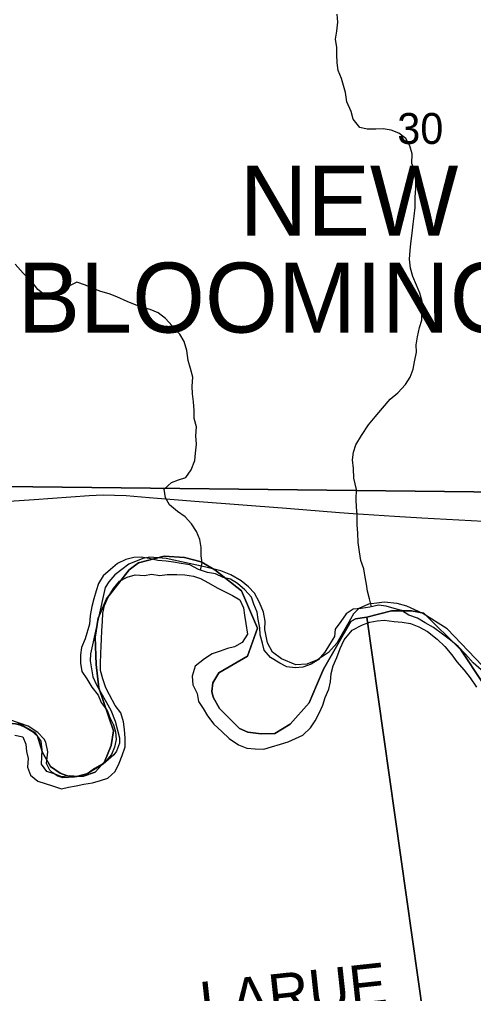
# Model space of a CAD drawing. Extents: x 1584893 to 1934202, y 663575 to 1091909.
# Drawn here: x 1744832 to 1748072, y 934048 to 941008 of the extents above; entities that cross this region are included whole.
import ezdxf

# ---------------------------------------------------------------- set-up
doc = ezdxf.new("R2010")
doc.units = 0
for name, color, linetype in [('GM_X_Corporation_Text', 7, 'Continuous'), ('GM_X_County_Road', 7, 'Continuous'), ('GM_X_County_Road_Text', 7, 'Continuous'), ('GM_X_Major_River', 7, 'Continuous'), ('GM_X_Minor_River', 7, 'Continuous'), ('GM_X_Section', 7, 'Continuous'), ('GM_X_Section_Text', 7, 'Continuous'), ('GM_X_Township', 7, 'Continuous')]:
    doc.layers.add(name, color=color, linetype=linetype)

msp = doc.modelspace()

# ---------------------------------------------------------------- linework, layer by layer
at = {"layer": 'GM_X_County_Road'}
for points in [[(1744705.4, 937566.6), (1744793.6, 937568.8), (1744936.5, 937577.9), (1745198.9, 937597.8), (1745330, 937606.9), (1745428.6, 937610.5), (1745510.8, 937610.1), (1745593, 937606.2), (1745756.7, 937593.6), (1746083.8, 937567), (1746738.2, 937515.2), (1747114.5, 937485.3), (1747212.4, 937478.5)], [(1747212.4, 937478.5), (1747507.4, 937458.3), (1747703.9, 937447.4), (1748408.5, 937408)]]:
    msp.add_lwpolyline(points, dxfattribs=at)
at = {"layer": 'GM_X_Major_River'}
for points in [[(1745878.1, 937137.5), (1745820.2, 937142.4), (1745756.3, 937155.5), (1745700.4, 937166.4), (1745648.3, 937163.3), (1745590, 937150.2), (1745531.5, 937121.1), (1745480.7, 937077.8), (1745429.9, 937032.5), (1745395, 936979), (1745378.1, 936925.1), (1745363.1, 936867.2), (1745348.2, 936813.3), (1745337.2, 936749.3), (1745330.2, 936687.3), (1745300.4, 936583.5), (1745273.3, 936519.8), (1745266.5, 936467.8), (1745267.5, 936409.7), (1745276.6, 936349.3), (1745311.8, 936296.7), (1745348.8, 936237.9), (1745393.9, 936179), (1745415.1, 936126.5), (1745458.2, 936069.7), (1745475.4, 936019.3), (1745502.6, 935968.7), (1745517.8, 935918.3), (1745520.9, 935862.1), (1745510, 935808.2), (1745489.2, 935756.4), (1745438.1, 935697.1), (1745367.4, 935656.1), (1745314.7, 935618.9), (1745250.3, 935599.9), (1745190.3, 935602.9), (1745134.1, 935595.8), (1745078.4, 935616.8), (1745026.6, 935635.7), (1744989.4, 935686.4), (1744990.3, 935740.5), (1744993.1, 935790.6), (1744986.1, 935850.9), (1744945, 935907.7), (1744893.4, 935940.6), (1744841.8, 935963.5), (1744783.9, 935978.5)], [(1748126.1, 936360.7), (1748068.9, 936411.8), (1748015.8, 936472.8), (1747962.7, 936527.8), (1747907.3, 936572.8), (1747852, 936615.8), (1747786.7, 936663), (1747727.1, 936696.1), (1747671.6, 936729.1), (1747609.9, 936752.2), (1747558.4, 936785.1), (1747506.6, 936800), (1747448.8, 936816.9), (1747394.8, 936823.8), (1747332.5, 936808.8), (1747270.3, 936799.8), (1747214.1, 936794.7), (1747163.5, 936761.5), (1747124.6, 936706), (1747083.6, 936650.5), (1747080.8, 936600.4), (1747043.8, 936540.9), (1747010.9, 936487.3), (1746963.9, 936431.9), (1746913.3, 936400.7), (1746854.9, 936379.6), (1746798.8, 936376.5), (1746740.9, 936383.5), (1746689.2, 936408.4), (1746623.8, 936449.5), (1746578.6, 936500.4), (1746565.4, 936550.8), (1746548.4, 936611.2), (1746547.2, 936661.3), (1746536.1, 936721.7), (1746529, 936773.9), (1746503.9, 936830.5), (1746486.7, 936880.9), (1746439.5, 936933.8), (1746388.2, 936978.7), (1746336.6, 937009.6), (1746284.7, 937020.5), (1746231.1, 937047.5), (1746173.2, 937056.4), (1746109.5, 937077.5), (1746047.9, 937110.6), (1745986, 937121.7), (1745930.1, 937130.6), (1745878.1, 937137.5)], [(1744798.6, 935894), (1744856.5, 935883.1), (1744877.6, 935830.6), (1744880.8, 935778.4), (1744894, 935728.1), (1744889, 935666), (1744910, 935607.5), (1744963.4, 935566.5), (1745067, 935532.7), (1745130.7, 935511.7), (1745181, 935522.8), (1745235.2, 935532), (1745291.4, 935543.1), (1745351.7, 935554.1), (1745410, 935569.2), (1745462.3, 935586.4), (1745515.2, 935633.7), (1745544.2, 935695.3), (1745565.1, 935749.1), (1745586.2, 935810.9), (1745585.2, 935873.1), (1745582.2, 935935.3), (1745573.1, 935989.6), (1745554.1, 936054.1), (1745514.9, 936106.8), (1745474.1, 936181.7), (1745446.9, 936232.3), (1745425.9, 936296.8), (1745410.8, 936355.2), (1745409.7, 936407.3), (1745412.8, 936477.4), (1745413.7, 936529.6), (1745416.5, 936579.6), (1745419.5, 936641.7), (1745424.6, 936705.8), (1745425.5, 936765.9), (1745438.4, 936819.9), (1745465.5, 936879.6), (1745502.5, 936941.1), (1745545.4, 936994.6), (1745600, 937023.7), (1745656.3, 937040.9), (1745724.3, 937035.7), (1745774.5, 937044.9), (1745834.4, 937035.9), (1745884.6, 937041.1), (1745954.7, 937042), (1746012.7, 937039), (1746072.6, 937030), (1746124.4, 937013.1), (1746180, 936982.1), (1746243.5, 936947), (1746299.1, 936918), (1746352.7, 936893.1), (1746404.2, 936860.2), (1746429.4, 936803.6), (1746436.5, 936751.4), (1746447.6, 936693), (1746458.3, 936616.7), (1746421.3, 936557.1), (1746366.7, 936525.9), (1746316.5, 936512.7), (1746264.1, 936495.5), (1746207.7, 936474.4), (1746153.1, 936439.2), (1746086.1, 936386.2), (1746065, 936316.4), (1746070, 936254.1), (1746099, 936191.5), (1746110.1, 936135.2), (1746143.3, 936084.5), (1746172.5, 936031.9), (1746217.6, 935973), (1746274.8, 935919.9), (1746328, 935870.9), (1746395.4, 935825.7), (1746455, 935800.7), (1746513, 935795.7), (1746575.1, 935794.7), (1746629.4, 935809.8), (1746693.8, 935830.8), (1746750.1, 935845.9), (1746802.6, 935871.2), (1746853, 935894.4), (1746907.9, 935945.6), (1746942.8, 935997.2), (1746971.7, 936050.8), (1746996.7, 936108.6), (1747013.6, 936162.4), (1747038.6, 936222.2), (1747051.5, 936276.1), (1747056.4, 936334.2), (1747069.4, 936390.1), (1747096.4, 936449.8), (1747121.4, 936513.5), (1747148.5, 936575.3), (1747205.7, 936644.5)], [(1747205.7, 936644.5), (1747280.4, 936683.4), (1747332.7, 936700.5), (1747385, 936711.7), (1747435.1, 936714.9), (1747507, 936705.7), (1747563, 936702.8), (1747622.9, 936691.8), (1747682.6, 936668.8), (1747744.2, 936635.7), (1747813.3, 936580.4), (1747866.5, 936527.4), (1747917.6, 936468.4), (1747952.9, 936417.7), (1748006, 936358.7), (1748049.1, 936303.8), (1748094.1, 936236.9)]]:
    msp.add_lwpolyline(points, dxfattribs=at)
at = {"layer": 'GM_X_Minor_River'}
for points in [[(1747344.6, 936811.7), (1747329.5, 936869), (1747314.4, 936923.4), (1747309.2, 936973.6), (1747300, 937023.9), (1747288.9, 937082.2), (1747267.9, 937142.7), (1747258.9, 937205), (1747250, 937271.3), (1747247, 937337.5), (1747242, 937397.8), (1747241.2, 937470), (1747238, 937522.2), (1747235, 937578.3), (1747238.1, 937648.5), (1747217.4, 937731), (1747216.5, 937799.2), (1747209.6, 937861.5), (1747214.5, 937917.5), (1747231.3, 937969.4), (1747272.5, 938034.9), (1747321.8, 938112.3), (1747370.8, 938169.6), (1747421.8, 938230.9), (1747477, 938296.2), (1747531.8, 938341.4), (1747586.8, 938400.6), (1747619.7, 938452.2), (1747640.7, 938510), (1747651.5, 938562), (1747664.7, 938629.9), (1747663.5, 938682.1), (1747672.5, 938740.1), (1747687.6, 938806), (1747704.5, 938859.8), (1747706.7, 938994.1), (1747689.6, 939052.5), (1747664.5, 939109.1), (1747639.5, 939171.7), (1747622.4, 939230.1), (1747615.5, 939294.3), (1747620.5, 939356.4), (1747625.3, 939408.5), (1747634.5, 939480.5), (1747641.6, 939544.5), (1747648.6, 939602.6), (1747655.6, 939664.6), (1747656.8, 939738.8), (1747659.8, 939800.9), (1747660.7, 939857), (1747649.9, 939929.3), (1747632.7, 939979.7), (1747633.8, 940047.9), (1747618.8, 940106.3), (1747589.6, 940156.9), (1747538.1, 940195.8), (1747484.4, 940216.7), (1747428.5, 940227.7), (1747374.4, 940224.6), (1747312.3, 940223.6), (1747260.5, 940236.4), (1747213.4, 940295.4), (1747198.3, 940349.7), (1747167.4, 940420.4), (1747158.5, 940486.7), (1747143.3, 940537.1), (1747130.1, 940587.4), (1747105, 940644), (1747097.9, 940698.2), (1747096.8, 940758.4), (1747095.7, 940808.5), (1747086.6, 940866.8), (1747097.6, 940924.8), (1747102.6, 940988.8), (1747099.6, 941047)], [(1746123.4, 937072.9), (1746136.3, 937125.2), (1746129.1, 937175.4), (1746128, 937235.6), (1746119, 937291.9), (1746095.9, 937348.4), (1746058.7, 937403.2), (1746013.5, 937454), (1745960.1, 937493), (1745902.8, 937540.1), (1745873.5, 937590.7), (1745864.6, 937653), (1745915.4, 937700.2), (1745965.8, 937719.5), (1746018.1, 937734.7), (1746057, 937790.2), (1746082.1, 937855.9), (1746087, 937910), (1746094.1, 937974), (1746091, 938034.2), (1746094.1, 938096.3), (1746079, 938156.7), (1746078, 938212.9), (1746073, 938277.1), (1746065.9, 938333.4), (1746064.8, 938387.5), (1746067.8, 938451.6), (1746052.9, 938514), (1746035.8, 938572.4), (1746026.9, 938642.8), (1746006, 938707.2), (1745976.8, 938759.9), (1745921.7, 938818.9), (1745874.5, 938871.8), (1745821.1, 938910.8), (1745765.4, 938935.7), (1745709.6, 938950.7), (1745651.9, 938971.7), (1745600.1, 938992.6), (1745526.6, 939025.9), (1745470.9, 939046.8), (1745413.1, 939063.8), (1745355.4, 939084.8), (1745301.7, 939109.8), (1745242, 939130.8), (1745183.4, 939101.7), (1745132.8, 939064.4), (1745068.3, 939039.4), (1745018.2, 939036.2), (1744962.8, 939079.2), (1744917.7, 939138.1), (1744858.6, 939195.2), (1744799.6, 939260.3)]]:
    msp.add_lwpolyline(points, dxfattribs=at)
at = {"layer": 'GM_X_Section'}
msp.add_lwpolyline([(1744794.1, 942974), (1750676.5, 942925.4), (1750594.8, 937603.3), (1744716.7, 937672), (1744790.8, 942835.4)], close=True, dxfattribs=at)
for points in [[(1744716.7, 937672), (1750594.8, 937603.3)], [(1748187.1, 936336.7), (1747883.9, 936653.5), (1747710.9, 936763.1), (1747597.4, 936816.1), (1747527.5, 936834.7), (1747435.6, 936843.5), (1747400, 936839.5), (1747321.5, 936830.5), (1747253.1, 936799.2), (1747214.8, 936761.5), (1747172.1, 936685.9), (1747096.9, 936550.5), (1747038.3, 936485), (1746957.8, 936431.7), (1746881.6, 936402.4), (1746803.5, 936397.1), (1746701.9, 936440), (1746636.3, 936486.6), (1746600.9, 936555), (1746583.7, 936649.1), (1746584.3, 936709.1), (1746572.8, 936773.2), (1746545.4, 936841.5), (1746510, 936907.8), (1746466.4, 936954.2), (1746412.8, 936996.7), (1746341.2, 937039.3), (1746269.4, 937068), (1746151.7, 937097), (1745878.2, 937157.5), (1745762.3, 937166.5), (1745712.2, 937157), (1745611.8, 937115.9), (1745513.1, 937040.8), (1745468.6, 936989.1), (1745442.3, 936949.4), (1745338, 936474.2), (1745335.5, 936424.3), (1745354.5, 936310.1), (1745382, 936253.8), (1745484.4, 936072.9), (1745513.7, 935994.6), (1745544.7, 935876.3), (1745544.3, 935836.3), (1745523.8, 935780.5), (1745505.5, 935752.7), (1745429, 935687.3), (1745318.3, 935620.3), (1745222.1, 935595.2), (1745140.1, 935589.9), (1745104.2, 935602.2), (1745064.4, 935626.6), (1745048.5, 935644.7), (1745025, 935692.9), (1745033.7, 935774.9), (1745020.3, 935845), (1745008.5, 935865.1), (1744962.9, 935913.5), (1744893.3, 935958.1), (1744691.9, 936028)]]:
    msp.add_lwpolyline(points, dxfattribs=at)
at = {"layer": 'GM_X_Township'}
for points in [[(1748137.4, 936270.1), (1747980.9, 936503.1), (1747716.7, 936765.1), (1747628.7, 936781.6), (1747486.9, 936782.6), (1747310.8, 936737), (1747230.1, 936725.5), (1747197, 936706.9), (1747001.4, 936364.9), (1746950.7, 936248.9), (1746900.1, 936124.5), (1746764.4, 935973.3), (1746654.7, 935906.9), (1746557.4, 935902.8), (1746462.1, 935915.2), (1746401, 935942), (1746258, 936084.9), (1746213.5, 936165.7), (1746205.1, 936207.2), (1746212.4, 936267.2), (1746253.8, 936339.8), (1746458.8, 936457.9), (1746530.1, 936659.9), (1746416.2, 936926), (1746225.5, 937075.1), (1746129.2, 937133.1), (1746009.1, 937163.1), (1745864.1, 937173.3), (1745680.9, 937124.6), (1745614.6, 937075.9), (1745452, 936868.6), (1745393.1, 936730.9), (1745371.4, 936594.2), (1745378.7, 936399.4), (1745397.5, 936231.7), (1745503.3, 935925.1), (1745486.7, 935819.4), (1745439.1, 935703.5), (1745372.9, 935630.9), (1745288, 935600.9), (1745192.7, 935595.6), (1745122.3, 935622.5), (1745053.9, 935670.1), (1744995.8, 935770.6), (1744959.6, 935886.6), (1744919.2, 935923.9), (1744836.3, 935973.5), (1744662.3, 935983.9)], [(1744662.3, 935983.9), (1744836.3, 935973.5), (1744919.2, 935923.9), (1744959.6, 935886.6), (1744995.8, 935770.6), (1745053.9, 935670.1), (1745122.3, 935622.5), (1745192.7, 935595.6), (1745288, 935600.9), (1745372.9, 935630.9), (1745439.1, 935703.5), (1745486.7, 935819.4), (1745503.3, 935925.1), (1745397.5, 936231.7), (1745378.7, 936399.4), (1745371.4, 936594.2), (1745393.1, 936730.9), (1745452, 936868.6), (1745614.6, 937075.9), (1745680.9, 937124.6), (1745864.1, 937173.3), (1746009.1, 937163.1), (1746129.2, 937133.1), (1746225.5, 937075.1), (1746416.2, 936926), (1746530.1, 936659.9), (1746458.8, 936457.9), (1746253.8, 936339.8), (1746212.4, 936267.2), (1746205.1, 936207.2), (1746213.5, 936165.7), (1746258, 936084.9), (1746401, 935942), (1746462.1, 935915.2), (1746557.4, 935902.8), (1746654.7, 935906.9), (1746764.4, 935973.3), (1746900.1, 936124.5), (1746950.7, 936248.9), (1747001.4, 936364.9), (1747197, 936706.9), (1747230.1, 936725.5), (1747310.8, 936737), (1747714.1, 933879.9)], [(1747714.1, 933879.9), (1747310.8, 936737), (1747486.9, 936782.6), (1747628.7, 936781.6), (1747716.7, 936765.1), (1747980.9, 936503.1), (1748137.4, 936270.1)]]:
    msp.add_lwpolyline(points, dxfattribs=at)

# ---------------------------------------------------------------- texts
at = {"layer": 'GM_X_Corporation_Text'}
for s, p in [('NEW', (1746403.9, 939463.2)), ('BLOOMINGTON', (1744817.7, 938770.9))]:
    msp.add_text(s, height=500, rotation=0.00001, dxfattribs=at).set_placement(p)
at = {"layer": 'GM_X_County_Road_Text'}
msp.add_text('LARUE', height=300, rotation=6.18117, dxfattribs=at).set_placement((1746136.4, 933829.5))
at = {"layer": 'GM_X_Section_Text'}
msp.add_text('30', height=221, rotation=0.00001, dxfattribs=at).set_placement((1747528, 940118.6))

doc.saveas('drawing.dxf')
